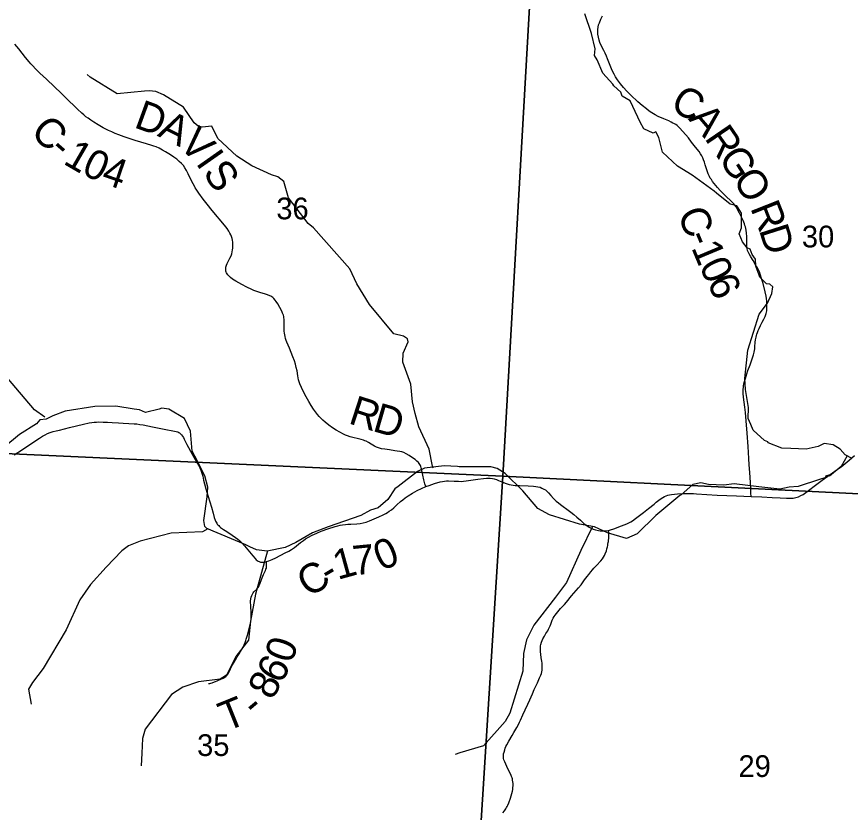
# Model space of a CAD drawing. Extents: x 396.2 to 468.4, y 232.6 to 279.1.
# Drawn here: x 421.533 to 423.138, y 268.52 to 270.053 of the extents above; entities that cross this region are included whole.
import ezdxf

# ---------------------------------------------------------------- set-up
doc = ezdxf.new("R2010")
doc.units = 0
for name, color, linetype in [('GM_X_County_Road', 7, 'Continuous'), ('GM_X_County_Road_Text', 7, 'Continuous'), ('GM_X_Minor_River', 7, 'Continuous'), ('GM_X_Section', 7, 'Continuous'), ('GM_X_Section_Text', 7, 'Continuous'), ('GM_X_Township_Road', 7, 'Continuous'), ('GM_X_Township_Road_Text', 7, 'Continuous')]:
    doc.layers.add(name, color=color, linetype=linetype)

msp = doc.modelspace()

# ---------------------------------------------------------------- linework, layer by layer
at = {"layer": 'GM_X_County_Road'}
for points in [[(422.7794, 269.8557), (422.7684, 269.8605), (422.7626, 269.8634), (422.7564, 269.8672), (422.7511, 269.8708), (422.7456, 269.8748), (422.7375, 269.8814), (422.7291, 269.8885), (422.7156, 269.9013), (422.7078, 269.9093), (422.7016, 269.9162), (422.6957, 269.9235), (422.6901, 269.931), (422.6864, 269.9369), (422.6836, 269.9419), (422.6811, 269.9465), (422.6784, 269.9523), (422.6709, 269.9711), (422.6686, 269.9765), (422.6663, 269.9821), (422.6636, 269.9875), (422.6586, 269.9971), (422.6561, 270.0028), (422.6545, 270.0076), (422.6532, 270.0131), (422.6523, 270.0186), (422.652, 270.0219), (422.6519, 270.0248), (422.652, 270.0279), (422.6526, 270.0323), (422.6536, 270.0366), (422.6551, 270.0407), (422.6582, 270.0475), (422.6611, 270.0541)], [(422.3211, 269.1476), (422.3194, 269.1527), (422.3171, 269.1608), (422.3153, 269.1694), (422.313, 269.1814), (422.3124, 269.1839), (422.3116, 269.1862), (422.3106, 269.1884), (422.3096, 269.1901), (422.3084, 269.192), (422.307, 269.1936), (422.3039, 269.1967), (422.3006, 269.1995), (422.2956, 269.2032), (422.2889, 269.2077), (422.2835, 269.2108), (422.2789, 269.2129), (422.2768, 269.2137), (422.2748, 269.2143), (422.2711, 269.2151), (422.2662, 269.2158), (422.2613, 269.2166), (422.2509, 269.218), (422.2424, 269.2193), (422.2358, 269.2205), (422.2299, 269.222), (422.2278, 269.2227), (422.2259, 269.2235), (422.2221, 269.2254), (422.2159, 269.2293), (422.2106, 269.2325), (422.2063, 269.2347), (422.2036, 269.2358), (422.2011, 269.2368), (422.1964, 269.2383), (422.1886, 269.2402), (422.1832, 269.2415), (422.1754, 269.2436), (422.1703, 269.2453), (422.1662, 269.2468), (422.1625, 269.2485), (422.1555, 269.2521), (422.1485, 269.2562), (422.1414, 269.2607), (422.1343, 269.2658), (422.127, 269.2715), (422.1228, 269.2753), (422.1195, 269.2785), (422.1158, 269.2824), (422.1124, 269.2864), (422.1088, 269.2913), (422.1049, 269.2969), (422.1006, 269.3036), (422.0958, 269.3112), (422.0907, 269.3204), (422.0858, 269.33), (422.0818, 269.3381), (422.0787, 269.3456), (422.0772, 269.3493), (422.076, 269.3529), (422.0751, 269.357), (422.0745, 269.3608), (422.0731, 269.3707), (422.0718, 269.3772), (422.0702, 269.3833), (422.068, 269.3899), (422.0652, 269.3975), (422.062, 269.4055), (422.0584, 269.4141), (422.0535, 269.4258), (422.0524, 269.4292), (422.0511, 269.433), (422.0501, 269.4368), (422.0494, 269.44), (422.0489, 269.4431), (422.0487, 269.4468), (422.0486, 269.4512), (422.0484, 269.457), (422.0485, 269.4638), (422.0483, 269.4694), (422.048, 269.4732), (422.0476, 269.4753), (422.047, 269.4776), (422.0455, 269.4816), (422.0437, 269.4855), (422.036, 269.4996), (422.0333, 269.504), (422.0312, 269.5067), (422.0282, 269.5101), (422.0265, 269.5115), (422.0249, 269.5128), (422.0228, 269.5141), (422.0209, 269.515), (422.0166, 269.5168), (422.0104, 269.5188), (422.0034, 269.521), (421.996, 269.5233), (421.9903, 269.5252), (421.9863, 269.527), (421.9764, 269.5317), (421.967, 269.5366), (421.9552, 269.5433), (421.9491, 269.5472), (421.9452, 269.5501), (421.9424, 269.5528), (421.9402, 269.5552), (421.9387, 269.5573), (421.9376, 269.5589), (421.9369, 269.5604), (421.9361, 269.5622), (421.9358, 269.5641), (421.9358, 269.5655), (421.9358, 269.5672), (421.9363, 269.5702), (421.9373, 269.5737), (421.9388, 269.5772), (421.9407, 269.581), (421.9441, 269.5872), (421.9463, 269.5922), (421.9475, 269.5959), (421.9483, 269.5994), (421.949, 269.6033), (421.9494, 269.6067), (421.9496, 269.6115), (421.9496, 269.6152), (421.9493, 269.6186), (421.9488, 269.622), (421.9482, 269.6255), (421.9472, 269.629), (421.9457, 269.6327), (421.944, 269.6359), (421.942, 269.6393), (421.9384, 269.6446), (421.9333, 269.651), (421.9098, 269.6791), (421.9, 269.6914), (421.8925, 269.7013), (421.8842, 269.7129), (421.8817, 269.7164), (421.8793, 269.7201), (421.8773, 269.7232), (421.8755, 269.7264), (421.8709, 269.7351), (421.8635, 269.7501), (421.8604, 269.7562), (421.8572, 269.7616), (421.8543, 269.7657), (421.8506, 269.77), (421.8465, 269.7739), (421.8418, 269.7779), (421.8363, 269.7819), (421.8296, 269.7865), (421.8201, 269.7924), (421.8141, 269.7958), (421.8075, 269.7991), (421.8017, 269.8016), (421.7977, 269.8031), (421.7936, 269.8045), (421.7834, 269.8076), (421.7722, 269.8109), (421.7615, 269.8142), (421.7537, 269.8166), (421.7463, 269.8191), (421.7404, 269.8212), (421.73, 269.8251), (421.7231, 269.8279), (421.7166, 269.8307), (421.7102, 269.8336), (421.7001, 269.8388), (421.6904, 269.8443), (421.682, 269.8496), (421.6763, 269.8533), (421.6711, 269.8569), (421.6668, 269.86), (421.6626, 269.8635), (421.6589, 269.8669), (421.6508, 269.8745), (421.645, 269.8801), (421.6335, 269.8913), (421.6192, 269.9052), (421.6061, 269.9177), (421.5908, 269.932), (421.5783, 269.944), (421.5699, 269.9519), (421.5643, 269.9576), (421.5607, 269.9615), (421.5573, 269.9654), (421.5505, 269.9741), (421.5374, 269.9906), (421.5301, 269.9996)], [(422.8646, 269.75), (422.8639, 269.7517), (422.8613, 269.7593), (422.859, 269.767), (422.8575, 269.7722), (422.8558, 269.777), (422.8542, 269.7807), (422.8522, 269.7844), (422.8497, 269.7885), (422.847, 269.7927), (422.8405, 269.8012), (422.8328, 269.811), (422.8264, 269.819), (422.8161, 269.8315), (422.8094, 269.8388), (422.807, 269.8409), (422.8047, 269.8428), (422.8022, 269.8446), (422.7996, 269.8463), (422.7968, 269.8478), (422.7936, 269.8494), (422.7886, 269.8517), (422.7794, 269.8557)], [(422.9471, 269.1283), (422.9469, 269.1347), (422.9465, 269.1453), (422.9453, 269.1652), (422.9448, 269.1745), (422.9438, 269.1893), (422.943, 269.2017), (422.9416, 269.2247), (422.9399, 269.2501), (422.9379, 269.2742), (422.9364, 269.2902), (422.9353, 269.3004), (422.9328, 269.3196), (422.9322, 269.327), (422.932, 269.3314), (422.9321, 269.3353), (422.9324, 269.3384), (422.9327, 269.3413), (422.9335, 269.3456), (422.9346, 269.3499), (422.9362, 269.3559), (422.9389, 269.3648), (422.9412, 269.3712), (422.9452, 269.3823), (422.9502, 269.3957), (422.9519, 269.401), (422.9532, 269.4064), (422.9538, 269.4094), (422.9542, 269.4129), (422.9546, 269.4168), (422.9552, 269.4255), (422.9559, 269.4304), (422.9569, 269.4353), (422.9576, 269.4382), (422.9585, 269.4413), (422.9596, 269.4446), (422.9609, 269.448), (422.9626, 269.4519), (422.9656, 269.4578), (422.9688, 269.4639), (422.9719, 269.4699), (422.9744, 269.4754), (422.9761, 269.481), (422.9767, 269.4837), (422.9772, 269.4863), (422.9776, 269.4889), (422.9777, 269.4915), (422.9778, 269.4957), (422.9777, 269.5), (422.9774, 269.5049), (422.9768, 269.5096), (422.9761, 269.5144), (422.9744, 269.5227), (422.9702, 269.5388), (422.9674, 269.5485), (422.9648, 269.5567), (422.9631, 269.5611), (422.9614, 269.565), (422.9593, 269.5689), (422.9566, 269.5735), (422.9511, 269.5831), (422.9466, 269.5901), (422.9434, 269.5955), (422.9416, 269.5996), (422.9406, 269.6025), (422.9398, 269.6062), (422.9393, 269.609), (422.9391, 269.6118), (422.9389, 269.6181), (422.9388, 269.6295), (422.9384, 269.6358), (422.9376, 269.6415), (422.937, 269.6447), (422.9362, 269.6475), (422.9354, 269.6505), (422.9345, 269.6534), (422.9333, 269.6567), (422.9318, 269.6603), (422.9289, 269.6664), (422.925, 269.674), (422.9213, 269.681), (422.9182, 269.6863), (422.9162, 269.6893), (422.9137, 269.6924), (422.9108, 269.6955), (422.9071, 269.6991), (422.9007, 269.7049), (422.897, 269.7083), (422.8935, 269.7118), (422.8879, 269.7177), (422.8825, 269.7237), (422.8761, 269.7311), (422.8732, 269.7349), (422.8707, 269.7387), (422.8687, 269.7418), (422.867, 269.7448), (422.8654, 269.7483), (422.8646, 269.75)], [(421.5288, 269.2085), (421.5447, 269.219), (421.561, 269.2299), (421.5771, 269.2408), (421.5833, 269.2445), (421.5881, 269.2471), (421.593, 269.2495), (421.5979, 269.2514), (421.6039, 269.2533), (421.6092, 269.2548), (421.6159, 269.2565), (421.6353, 269.2612), (421.6621, 269.2677), (421.6733, 269.27), (421.6781, 269.2708), (421.6825, 269.2713), (421.687, 269.2717), (421.6917, 269.272), (421.7, 269.2717), (421.708, 269.2714), (421.7176, 269.2708), (421.7298, 269.2702), (421.7384, 269.2698), (421.7492, 269.2692), (421.7599, 269.2686), (421.7648, 269.2682), (421.7706, 269.2674), (421.7772, 269.2665), (421.7948, 269.2629), (421.8174, 269.258), (421.8373, 269.2544), (421.8406, 269.2536), (421.8435, 269.2528), (421.8454, 269.2519), (421.8472, 269.2508), (421.8491, 269.2493), (421.8509, 269.2472), (421.8526, 269.2448), (421.8543, 269.242), (421.856, 269.2388), (421.861, 269.2286), (421.8712, 269.2102), (421.8802, 269.1942), (421.8834, 269.1885), (421.8861, 269.1834), (421.8879, 269.1793), (421.8893, 269.1755), (421.8905, 269.1715), (421.8916, 269.1674), (421.8933, 269.1596), (421.895, 269.1529), (421.8979, 269.1429), (421.9023, 269.1284), (421.9083, 269.1077), (421.9117, 269.096), (421.9139, 269.0882), (421.9157, 269.0831), (421.9164, 269.0811), (421.9174, 269.0791), (421.9185, 269.0772), (421.9197, 269.0754), (421.9209, 269.0739), (421.9224, 269.0723), (421.924, 269.0707), (421.9261, 269.0689), (421.9316, 269.065), (421.9382, 269.0607), (421.9484, 269.0542), (421.955, 269.0497), (421.9594, 269.0463), (421.9626, 269.0435), (421.967, 269.0391), (421.9723, 269.0331), (421.988, 269.0139), (421.9926, 269.0087), (421.9948, 269.0067), (421.9967, 269.0051), (421.9986, 269.0039), (422.0004, 269.0031), (422.0029, 269.0022), (422.0055, 269.0018), (422.0081, 269.0017), (422.0113, 269.0021), (422.0147, 269.003), (422.0186, 269.0044), (422.0251, 269.0072), (422.0323, 269.0104), (422.0506, 269.0197), (422.0572, 269.0233), (422.0625, 269.0266), (422.0681, 269.0305), (422.0799, 269.0397), (422.0853, 269.0438), (422.0894, 269.0466), (422.0951, 269.0502), (422.1022, 269.0539), (422.1113, 269.0579), (422.1199, 269.0614), (422.1327, 269.0659), (422.1468, 269.0706), (422.1516, 269.0719), (422.1559, 269.0729), (422.1607, 269.0738), (422.1667, 269.0747), (422.171, 269.0751), (422.1766, 269.0754), (422.1884, 269.0757), (422.1947, 269.0763), (422.2002, 269.0774), (422.2063, 269.0792), (422.2127, 269.0815), (422.2214, 269.0851), (422.2304, 269.0892), (422.2389, 269.0931), (422.2442, 269.0959), (422.2474, 269.0977), (422.2508, 269.1), (422.2549, 269.103), (422.2592, 269.1066), (422.2654, 269.1121), (422.2722, 269.1185), (422.2767, 269.1223), (422.2816, 269.1261), (422.2873, 269.1299), (422.2955, 269.1348), (422.3043, 269.1397), (422.3128, 269.1439), (422.3211, 269.1476), (422.3272, 269.1499), (422.338, 269.1534), (422.3489, 269.1564), (422.3529, 269.1574), (422.3568, 269.1582), (422.3606, 269.1585), (422.3646, 269.1587), (422.3754, 269.1582), (422.384, 269.1578), (422.3896, 269.1576), (422.3939, 269.1578), (422.3988, 269.1583), (422.4211, 269.1615), (422.4324, 269.163), (422.4379, 269.1635), (422.4413, 269.1636), (422.4449, 269.1636), (422.4491, 269.1631), (422.4529, 269.1622), (422.457, 269.161), (422.4611, 269.1594), (422.4705, 269.1552), (422.4759, 269.1532), (422.4813, 269.1516), (422.4852, 269.1507), (422.4889, 269.1502), (422.4932, 269.1498), (422.5013, 269.1493), (422.5179, 269.1489), (422.5284, 269.1483), (422.5328, 269.1478), (422.5368, 269.1472), (422.5409, 269.1461), (422.5447, 269.1446), (422.5484, 269.1428), (422.5512, 269.141), (422.5543, 269.1386), (422.5575, 269.1356), (422.5618, 269.1306), (422.567, 269.1246), (422.5722, 269.1193), (422.5762, 269.116), (422.5805, 269.1127), (422.5852, 269.1093), (422.5928, 269.1039), (422.6003, 269.0982), (422.6057, 269.0939), (422.612, 269.0887), (422.6185, 269.0827), (422.6253, 269.0767), (422.6318, 269.0717), (422.6354, 269.0694), (422.6393, 269.0672), (422.6434, 269.0656), (422.6477, 269.0642), (422.6532, 269.063), (422.6569, 269.0625), (422.6596, 269.0623), (422.6631, 269.0622), (422.6675, 269.0624), (422.6728, 269.0632), (422.6768, 269.0643), (422.683, 269.0662), (422.6976, 269.0716), (422.7079, 269.0759), (422.7119, 269.0777), (422.7154, 269.0796), (422.7189, 269.0818), (422.725, 269.0861), (422.7401, 269.0975), (422.7499, 269.1053), (422.7606, 269.1139), (422.7646, 269.1173), (422.7697, 269.1214), (422.7739, 269.1243), (422.7773, 269.1264), (422.7805, 269.1282), (422.7838, 269.1298), (422.7867, 269.1308), (422.7903, 269.1317), (422.794, 269.1324), (422.7996, 269.133), (422.8053, 269.1334), (422.8177, 269.134), (422.8299, 269.1341), (422.8361, 269.134), (422.8422, 269.1338), (422.882, 269.1313), (422.9192, 269.1294), (422.9471, 269.1283), (422.9676, 269.1275), (422.9875, 269.1265), (423.0034, 269.1256), (423.0153, 269.1249), (423.0226, 269.1249), (423.0283, 269.1253), (423.0333, 269.1262), (423.0383, 269.1279), (423.0431, 269.1301), (423.0473, 269.1325), (423.0527, 269.1362), (423.0604, 269.1419), (423.0687, 269.1481), (423.0843, 269.1596), (423.0996, 269.1709), (423.1127, 269.1802), (423.1204, 269.1858), (423.1284, 269.1918), (423.136, 269.1982), (423.1465, 269.2076)], [(422.4691, 268.5194), (422.4725, 268.5233), (422.4752, 268.5268), (422.4766, 268.5291), (422.4778, 268.5315), (422.4789, 268.5338), (422.4808, 268.5386), (422.4839, 268.5477), (422.4866, 268.5562), (422.4878, 268.5607), (422.4883, 268.5639), (422.4887, 268.5674), (422.489, 268.5715), (422.489, 268.5758), (422.4887, 268.5786), (422.4881, 268.582), (422.4876, 268.5844), (422.4871, 268.5864), (422.4862, 268.589), (422.4852, 268.5912), (422.4828, 268.5966), (422.4791, 268.6042), (422.4729, 268.6173), (422.4715, 268.621), (422.4708, 268.6235), (422.4704, 268.627), (422.4706, 268.6301), (422.4709, 268.633), (422.4716, 268.6363), (422.4729, 268.6407), (422.4737, 268.6436), (422.4749, 268.6466), (422.4768, 268.6503), (422.4809, 268.6574), (422.4872, 268.6684), (422.4903, 268.6736), (422.496, 268.6835), (422.4993, 268.6895), (422.5014, 268.6935), (422.5033, 268.6975), (422.508, 268.7076), (422.5126, 268.7177), (422.5173, 268.7283), (422.5212, 268.737), (422.5262, 268.7486), (422.5297, 268.7564), (422.5328, 268.7628), (422.536, 268.7697), (422.5402, 268.779), (422.5424, 268.7841), (422.5436, 268.7876), (422.5443, 268.7907), (422.5448, 268.794), (422.545, 268.7976), (422.545, 268.8018), (422.5448, 268.8073), (422.5443, 268.811), (422.5432, 268.8177), (422.5422, 268.8248), (422.5418, 268.8291), (422.5416, 268.8328), (422.5416, 268.8358), (422.542, 268.8405), (422.5424, 268.8433), (422.5436, 268.8478), (422.545, 268.8512), (422.5462, 268.854), (422.5492, 268.8592), (422.5524, 268.8644), (422.5559, 268.87), (422.5574, 268.8727), (422.5591, 268.8765), (422.5602, 268.8792), (422.5614, 268.8828), (422.5627, 268.8863), (422.5637, 268.8885), (422.5645, 268.8905), (422.5662, 268.894), (422.5683, 268.8973), (422.5701, 268.8999), (422.5727, 268.9033), (422.5806, 268.9128), (422.5878, 268.9207), (422.5918, 268.9252), (422.6018, 268.9374), (422.6104, 268.9471), (422.6151, 268.9522), (422.6199, 268.9581), (422.6268, 268.9676), (422.6318, 268.9746), (422.6346, 268.9781), (422.6386, 268.9833), (422.642, 268.9872), (422.6447, 268.9902), (422.6476, 268.9934), (422.6499, 268.9957), (422.658, 269.0047), (422.6611, 269.0083), (422.6633, 269.0114), (422.665, 269.0147), (422.6665, 269.0181), (422.6686, 269.0239), (422.6697, 269.0276), (422.6707, 269.0315), (422.6712, 269.0339), (422.6717, 269.0366), (422.6723, 269.0395), (422.6726, 269.0415), (422.6729, 269.0441), (422.6732, 269.0473), (422.6735, 269.0519), (422.6734, 269.0555), (422.6732, 269.0587), (422.6728, 269.0632)]]:
    msp.add_lwpolyline(points, dxfattribs=at)
at = {"layer": 'GM_X_Minor_River'}
for points in [[(423.1418, 269.2019), (423.1286, 269.2087), (423.1187, 269.2193), (423.1051, 269.228), (423.0877, 269.2306), (423.0764, 269.2249), (423.0529, 269.2195), (423.0235, 269.2206), (423.0064, 269.2213), (422.9803, 269.2315), (422.9796, 269.2334), (422.9728, 269.2361), (422.9512, 269.2565), (422.947, 269.2672), (422.9417, 269.2789), (422.9421, 269.2998), (422.9364, 269.3348), (422.9349, 269.3557), (422.9412, 269.4101), (422.9627, 269.4793), (422.9786, 269.5006), (422.9873, 269.5192), (422.9888, 269.5322), (422.9835, 269.5371), (422.9767, 269.5382), (422.9642, 269.5511), (422.9627, 269.5549), (422.9562, 269.572), (422.9554, 269.5857), (422.9494, 269.5944), (422.9456, 269.605), (422.9399, 269.6073), (422.9308, 269.6191), (422.9244, 269.6343), (422.9285, 269.6461), (422.9285, 269.6742), (422.9221, 269.6841), (422.9198, 269.6882), (422.907, 269.6912), (422.8805, 269.7128), (422.8759, 269.7166), (422.8339, 269.7473), (422.8056, 269.7644), (422.7863, 269.7829), (422.7768, 269.7917), (422.7696, 269.8201), (422.7639, 269.8308), (422.7586, 269.8285), (422.7409, 269.8364), (422.7337, 269.8493), (422.7197, 269.8793), (422.7147, 269.8903), (422.6992, 269.8998), (422.6962, 269.907), (422.683, 269.9191), (422.6811, 269.9229), (422.6621, 269.9438), (422.6508, 269.9692), (422.6458, 269.978), (422.647, 269.9909), (422.6398, 270.0205), (422.6269, 270.0581)], [(422.3355, 269.1829), (422.3339, 269.1866), (422.3277, 269.2198), (422.3075, 269.2626), (422.3007, 269.2886), (422.2953, 269.3108), (422.2922, 269.3451), (422.2769, 269.387), (422.2774, 269.4044), (422.2868, 269.4262), (422.2858, 269.4319), (422.278, 269.4371), (422.2596, 269.4415), (422.2126, 269.4984), (422.1881, 269.5379), (422.1746, 269.5672), (422.1048, 269.6461), (422.0945, 269.6541), (422.057, 269.7035), (422.0478, 269.7349), (422.0363, 269.7444), (422.024, 269.7482), (421.9859, 269.765), (421.957, 269.7841), (421.9206, 269.818), (421.9089, 269.8415), (421.8907, 269.8398), (421.8828, 269.8416), (421.8751, 269.8483), (421.8544, 269.8782), (421.8158, 269.9022), (421.8013, 269.9083), (421.7885, 269.9099), (421.7794, 269.9094), (421.7271, 269.9043), (421.6751, 269.9363), (421.6689, 269.9414)], [(421.5876, 269.2811), (421.5676, 269.2954), (421.5136, 269.359), (421.5026, 269.381), (421.4526, 269.4646), (421.4391, 269.4958), (421.3612, 269.6072), (421.3453, 269.6283)], [(423.1319, 269.207), (423.1206, 269.1859), (423.098, 269.1679), (423.0987, 269.1702), (423.0904, 269.1675), (423.0908, 269.1649), (423.0787, 269.1614), (423.0379, 269.1477), (423.0205, 269.1461), (423.0027, 269.1426), (422.9623, 269.1471), (422.9146, 269.1531), (422.895, 269.1504), (422.8651, 269.1518), (422.8504, 269.1548), (422.8349, 269.1517), (422.8126, 269.1319), (422.8103, 269.1304), (422.7639, 269.0919), (422.728, 269.0565), (422.7072, 269.0477), (422.6705, 269.0586), (422.6456, 269.07), (422.6172, 269.0752), (422.5594, 269.093), (422.5367, 269.1054), (422.5075, 269.1392), (422.4739, 269.1729), (422.4583, 269.1824), (422.4459, 269.1854), (422.3854, 269.1853), (422.382, 269.186), (422.3563, 269.1875), (422.3185, 269.1829), (422.3049, 269.1767), (422.2679, 269.1474), (422.2614, 269.1432), (422.2482, 269.1226), (422.2293, 269.1063), (422.2146, 269.102), (422.1957, 269.0917), (422.1333, 269.0699), (422.1027, 269.0585), (422.071, 269.0401), (422.0506, 269.0302), (422.0154, 269.0233), (421.9954, 269.0259), (421.9826, 269.0312), (421.9746, 269.0354), (421.8997, 269.0667), (421.8959, 269.0709), (421.8937, 269.0823), (421.9001, 269.1275), (421.9015, 269.1465), (421.8955, 269.1682), (421.8765, 269.2058), (421.8716, 269.216), (421.8678, 269.254), (421.8568, 269.2787), (421.8266, 269.2965), (421.8129, 269.2988), (421.8077, 269.2968), (421.7816, 269.2899), (421.7699, 269.2956), (421.7596, 269.2967), (421.7245, 269.3027), (421.684, 269.3015), (421.6266, 269.2926), (421.6028, 269.2838), (421.5903, 269.2773), (421.5778, 269.2758), (421.5714, 269.2682), (421.5386, 269.2476), (421.4777, 269.198)], [(422.6421, 269.0706), (422.6197, 269.0244), (422.5917, 268.9627), (422.5705, 268.9345), (422.5291, 268.8804), (422.515, 268.8523), (422.509, 268.8263), (422.5079, 268.7922), (422.4828, 268.7114), (422.474, 268.6953), (422.4321, 268.6484), (422.3867, 268.6347), (422.3776, 268.6316)], [(421.9017, 269.0659), (421.8909, 269.0606), (421.8306, 269.0575), (421.771, 269.0427), (421.7486, 269.0334), (421.7361, 269.0239), (421.7059, 268.9922), (421.6758, 268.959), (421.6552, 268.9294), (421.6287, 268.8714), (421.5847, 268.7972), (421.5641, 268.77), (421.5565, 268.7571), (421.5612, 268.7282)], [(422.0166, 269.0235), (421.993, 268.94), (421.9835, 268.8883), (421.9798, 268.852), (421.9554, 268.8201), (421.9373, 268.7846), (421.9253, 268.7763), (421.8832, 268.7712), (421.8534, 268.7615), (421.8318, 268.747), (421.781, 268.6803), (421.776, 268.6626), (421.7747, 268.6338), (421.7732, 268.6099)]]:
    msp.add_lwpolyline(points, dxfattribs=at)
at = {"layer": 'GM_X_Section'}
for points in [[(422.5263, 270.1736), (422.4695, 269.1674), (421.4251, 269.2153), (421.4857, 270.2238)], [(422.5263, 270.1736), (423.5677, 270.1204), (423.5437, 269.7436), (423.5236, 269.4184), (423.5049, 269.1191), (423.5049, 269.1165), (422.4695, 269.1674)], [(422.4695, 269.1674), (422.4038, 268.126), (421.3567, 268.1769), (421.4251, 269.2153)], [(422.4695, 269.1674), (423.5049, 269.1165), (423.4737, 268.598), (423.4418, 268.0724), (422.4038, 268.126)]]:
    msp.add_lwpolyline(points, close=True, dxfattribs=at)
at = {"layer": 'GM_X_Township_Road'}
msp.add_lwpolyline([(421.903, 268.7681), (421.9051, 268.7684), (421.9071, 268.7689), (421.9096, 268.7697), (421.9209, 268.7742), (421.9262, 268.7765), (421.9308, 268.7786), (421.9342, 268.7805), (421.9359, 268.7817), (421.9378, 268.7835), (421.9399, 268.7864), (421.943, 268.7922), (421.9451, 268.7964), (421.9491, 268.8045), (421.952, 268.8096), (421.9545, 268.8138), (421.958, 268.8196), (421.9617, 268.8254), (421.9646, 268.8301), (421.9675, 268.8352), (421.9694, 268.8385), (421.9715, 268.8424), (421.9735, 268.847), (421.9742, 268.849), (421.9748, 268.8511), (421.9755, 268.8534), (421.9778, 268.8613), (421.9797, 268.8683), (421.9812, 268.8741), (421.9829, 268.881), (421.9836, 268.8843), (421.9842, 268.8877), (421.9846, 268.8916), (421.9848, 268.8957), (421.9848, 268.8988), (421.9849, 268.9027), (421.984, 268.9196), (421.9837, 268.9234), (421.9837, 268.9268), (421.9842, 268.9311), (421.985, 268.9346), (421.9862, 268.938), (421.9875, 268.9405), (421.9888, 268.9426), (421.9903, 268.9446), (421.9955, 268.9501), (421.9972, 268.9521), (421.9982, 268.9533), (421.9994, 268.9552), (422.0003, 268.9569), (422.0018, 268.9598), (422.0047, 268.9683), (422.006, 268.972), (422.0071, 268.9749), (422.0085, 268.9781), (422.0111, 268.9832), (422.0123, 268.9861), (422.0133, 268.9886), (422.0141, 268.9907), (422.0145, 268.9929), (422.0147, 268.9955), (422.0147, 269.003)], dxfattribs=at)

# ---------------------------------------------------------------- texts
at = {"layer": 'GM_X_County_Road_Text'}
for s, rotation, p in [('C', 329.1581, (422.7887, 269.8762)), ('D', 340.0016, (421.7573, 269.8401)), ('A', 310.3338, (422.825, 269.8555)), ('C', 315.2926, (421.5578, 269.8282)), ('A', 333.7917, (421.8028, 269.8236)), ('V', 314.687, (421.8436, 269.8045)), ('R', 304.3959, (422.8564, 269.8186)), ('-', 318.6757, (421.5936, 269.7929)), ('1', 329.9072, (421.621, 269.7704)), ('0', 334.9905, (421.6562, 269.7503)), ('I', 305.0173, (421.8771, 269.7708)), ('G', 303.4335, (422.8827, 269.7803)), ('4', 341.0668, (421.694, 269.7331)), ('S', 304.5862, (421.8904, 269.7518)), ('O', 303.194, (422.9102, 269.7386)), ('R', 291.5072, (422.9451, 269.6845)), ('C', 292.4711, (422.8046, 269.6729)), ('D', 287.6504, (422.9619, 269.642)), ('-', 292.5162, (422.8225, 269.6297)), ('1', 292.6769, (422.8315, 269.608)), ('0', 295.4696, (422.8462, 269.5729)), ('6', 295.758, (422.8614, 269.5411)), ('R', 342.1118, (422.1701, 269.27)), ('D', 343.9296, (422.2164, 269.2551)), ('7', 5.6189, (422.1826, 268.9765)), ('0', 22.8253, (422.2354, 268.9844)), ('1', 15.4032, (422.1513, 268.9676)), ('C', 32.0401, (422.0957, 268.9327)), ('-', 30.8138, (422.135, 268.9573))]:
    msp.add_text(s, height=0.0568, rotation=rotation, dxfattribs=at).set_placement(p)
at = {"layer": 'GM_X_Section_Text'}
for s, p in [('36', (422.0333, 269.6623)), ('30', (423.045, 269.6082)), ('35', (421.8808, 268.6286)), ('29', (422.9229, 268.5882))]:
    msp.add_text(s, height=0.04186, rotation=0, dxfattribs=at).set_placement(p)
at = {"layer": 'GM_X_Township_Road_Text'}
for s, rotation, p in [('0', 70.935, (422.0629, 268.8053)), ('6', 61.4261, (422.0421, 268.7652)), ('8', 62.0232, (422.0257, 268.7344)), ('T', 21.8814, (421.9368, 268.6752)), ('-', 39.982, (421.9929, 268.701))]:
    msp.add_text(s, height=0.0568, rotation=rotation, dxfattribs=at).set_placement(p)

doc.saveas('drawing.dxf')
